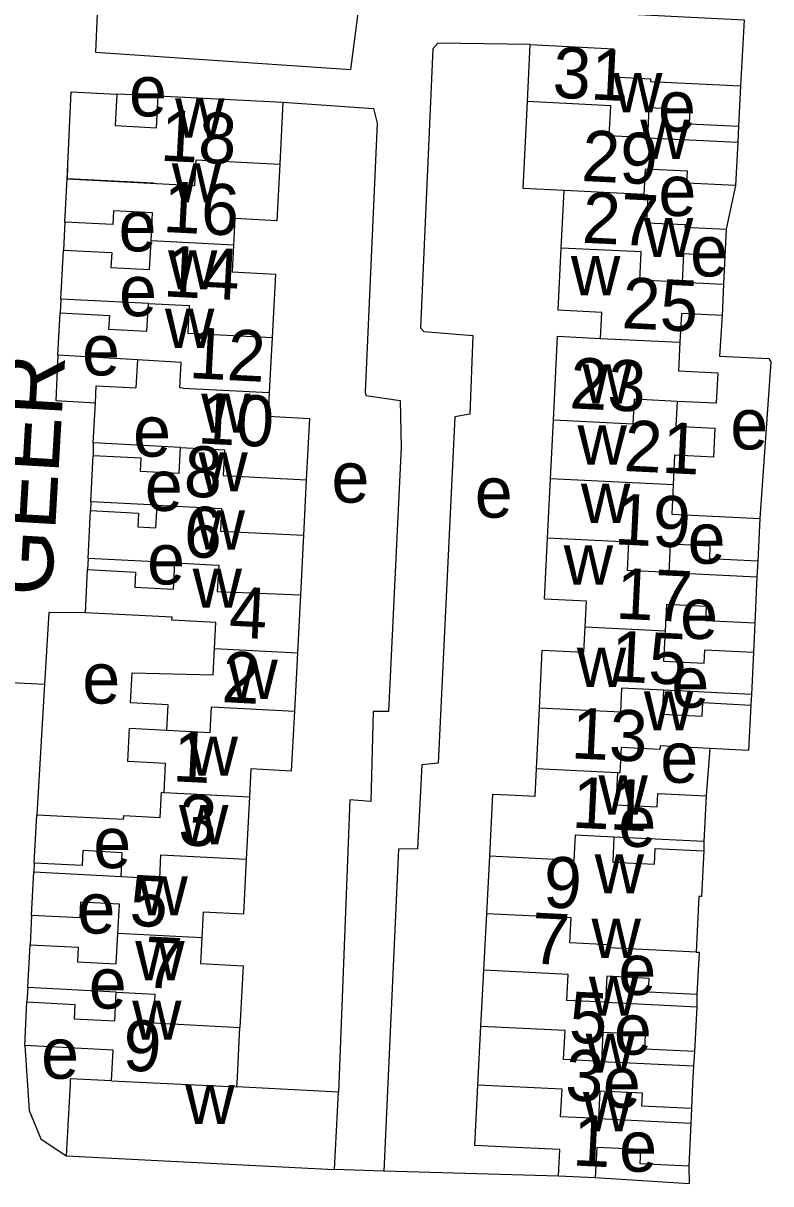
# Model space of a CAD drawing. Extents: x 163026 to 166241, y 382475 to 384501.
# Drawn here: x 164462 to 164520.6, y 383742.2 to 383833.2 of the extents above; entities that cross this region are included whole.
import ezdxf

# ---------------------------------------------------------------- set-up
doc = ezdxf.new("R2010")
doc.units = 0
for name, color, linetype in [('BLT_Basislijn', 7, 'Continuous'), ('BLT_Bebouwing', 7, 'Continuous'), ('BLT_Centroide', 7, 'Continuous'), ('BLT_Huisnummer', 7, 'Continuous'), ('BLT_Huisnummer_ tussenligend', 7, 'Continuous'), ('BLT_Onderverdeling_panden', 7, 'Continuous'), ('BLT_Straatnaam', 7, 'Continuous')]:
    doc.layers.add(name, color=color, linetype=linetype)

msp = doc.modelspace()

# ---------------------------------------------------------------- linework, layer by layer
at = {"layer": 'BLT_Basislijn'}
for p, q in [((164518.507, 383833.438), (164518.209, 383828.262)), ((164518.052, 383825.077), (164517.99, 383823.851)), ((164465.42, 383821.932), (164465.392, 383820.979)), ((164517.824, 383820.464), (164517.093, 383817.028)), ((164465.217, 383817.583), (164465.109, 383815.398)), ((164516.989, 383814.928), (164516.88, 383812.713)), ((164464.911, 383811.553), (164464.849, 383810.47)), ((164467.447, 383800.264), (164467.434, 383799.283)), ((164467.247, 383795.658), (164467.231, 383794.964)), ((164467.037, 383791.21), (164467.002, 383790.331)), ((164519.557, 383790.989), (164519.5, 383789.774)), ((164519.321, 383786.129), (164519.234, 383783.866)), ((164457.682, 383781.642), (164463.611, 383781.358)), ((164463.611, 383781.358), (164463.012, 383771.109)), ((164519.075, 383780.544), (164519.02, 383779.71)), ((164515.792, 383776.31), (164515.509, 383772.591)), ((164515.333, 383769.013), (164515.325, 383768.268)), ((164462.817, 383767.319), (164462.781, 383766.623)), ((164462.605, 383763.208), (164462.491, 383760.912)), ((164462.319, 383757.561), (164462.245, 383756.429)), ((164514.791, 383757.007), (164514.782, 383756.049)), ((164514.609, 383752.54), (164514.515, 383751.413)), ((164514.358, 383748.06), (164514.323, 383746.917)), ((164490.233, 383743.166), (164486.369, 383743.278)), ((164503.94, 383742.767), (164490.233, 383743.166))]:
    msp.add_line(p, q, dxfattribs=at)
for points in [[(164468.388, 383848.483), (164467.628, 383830.903), (164487.65, 383829.556), (164488.351, 383834.974), (164518.507, 383833.438)], [(164501.724, 383831.51), (164494.483, 383831.615), (164494.088, 383831.182), (164493.1, 383809.306), (164493.368, 383809.019), (164497.211, 383808.681), (164496.969, 383802.53), (164495.809, 383802.326), (164494.502, 383775.154), (164493.227, 383775.015), (164492.869, 383768.445), (164491.379, 383768.397), (164490.233, 383743.166)], [(164472.541, 383827.499), (164469.284, 383827.619)], [(164482.324, 383826.996), (164489.416, 383826.497), (164489.722, 383825.349), (164488.766, 383804.251), (164488.829, 383803.996), (164491.519, 383803.601), (164491.602, 383799.936), (164490.614, 383779.201), (164489.407, 383779.195), (164489.228, 383772.148), (164487.557, 383772.267), (164486.682, 383749.35)], [(164516.76, 383810.256), (164516.564, 383807.084), (164520.426, 383806.884), (164520.585, 383806.629), (164519.722, 383794.333)], [(164464.678, 383807.155), (164464.501, 383803.598), (164467.609, 383803.423)], [(164466.83, 383786.943), (164463.951, 383786.965), (164463.611, 383781.358)], [(164462.069, 383753.01), (164462.409, 383747.923), (164463.325, 383745.691), (164465.316, 383744.363)], [(164514.157, 383743.544), (164514.176, 383742.167), (164506.812, 383742.626)]]:
    msp.add_lwpolyline(points, dxfattribs=at)
at = {"layer": 'BLT_Bebouwing'}
for p, q in [((164501.503, 383827.032), (164501.724, 383831.51)), ((164518.209, 383828.262), (164518.052, 383825.077)), ((164472.541, 383827.499), (164482.324, 383826.996)), ((164482.324, 383826.996), (164482.074, 383822.138)), ((164517.99, 383823.851), (164517.824, 383820.464)), ((164465.217, 383817.583), (164465.392, 383820.98)), ((164472.175, 383820.63), (164465.392, 383820.979)), ((164504.154, 383815.544), (164504.376, 383820.054)), ((164517.093, 383817.028), (164516.989, 383814.928)), ((164464.911, 383811.553), (164465.109, 383815.398)), ((164516.88, 383812.713), (164516.76, 383810.256)), ((164464.678, 383807.155), (164464.849, 383810.47)), ((164481.476, 383808.539), (164481.254, 383804.218)), ((164503.537, 383802.055), (164503.862, 383808.634)), ((164503.862, 383808.634), (164507.239, 383808.464)), ((164470.904, 383806.783), (164464.678, 383807.155)), ((164470.904, 383806.783), (164470.779, 383804.578)), ((164467.447, 383800.264), (164467.609, 383803.423)), ((164503.313, 383797.463), (164503.537, 383802.055)), ((164467.247, 383795.658), (164467.434, 383799.283)), ((164484.156, 383797.368), (164483.933, 383793.023)), ((164503.08, 383792.789), (164503.313, 383797.463)), ((164467.037, 383791.21), (164467.231, 383794.964)), ((164519.722, 383794.333), (164519.557, 383790.989)), ((164483.933, 383793.023), (164483.692, 383788.365)), ((164466.83, 383786.943), (164467.002, 383790.331)), ((164519.5, 383789.774), (164519.321, 383786.129)), ((164483.692, 383788.365), (164483.457, 383783.81)), ((164483.457, 383783.81), (164483.222, 383779.233)), ((164519.234, 383783.866), (164519.075, 383780.544)), ((164502.199, 383774.699), (164502.432, 383779.464)), ((164479.697, 383772.518), (164479.447, 383767.631)), ((164515.509, 383772.591), (164515.333, 383769.013)), ((164462.817, 383767.319), (164463.012, 383771.109)), ((164498.316, 383763.347), (164498.537, 383767.856)), ((164515.325, 383768.268), (164515.149, 383764.697)), ((164462.605, 383763.208), (164462.781, 383766.623)), ((164498.073, 383758.908), (164498.316, 383763.347)), ((164462.319, 383757.561), (164462.491, 383760.912)), ((164514.955, 383760.327), (164514.791, 383757.007)), ((164497.844, 383754.503), (164498.073, 383758.908)), ((164462.069, 383753.01), (164462.245, 383756.429)), ((164514.782, 383756.049), (164514.609, 383752.54)), ((164514.515, 383751.413), (164514.445, 383750)), ((164486.682, 383749.35), (164478.717, 383749.758)), ((164514.445, 383750), (164514.358, 383748.06)), ((164486.369, 383743.278), (164486.682, 383749.35)), ((164514.323, 383746.917), (164514.157, 383743.544)), ((164465.316, 383744.363), (164486.369, 383743.278)), ((164506.812, 383742.626), (164503.94, 383742.767))]:
    msp.add_line(p, q, dxfattribs=at)
for points in [[(164501.724, 383831.51), (164508.258, 383831.188), (164508.149, 383828.981), (164511.159, 383828.833), (164511.148, 383828.609), (164518.209, 383828.262)], [(164465.392, 383820.98), (164465.722, 383827.803), (164469.284, 383827.619)], [(164469.284, 383827.619), (164469.157, 383825.153), (164472.413, 383824.985), (164472.541, 383827.499)], [(164504.376, 383820.054), (164501.168, 383820.21), (164501.503, 383827.032)], [(164518.052, 383825.077), (164514.198, 383825.267), (164514.254, 383826.401), (164511.025, 383826.56), (164510.909, 383824.2)], [(164510.909, 383824.2), (164517.99, 383823.851)], [(164482.074, 383822.138), (164481.846, 383817.697), (164478.55, 383817.866), (164478.442, 383815.777)], [(164517.824, 383820.464), (164513.997, 383820.653), (164514.043, 383821.586), (164510.724, 383821.749), (164510.625, 383819.745)], [(164510.625, 383819.745), (164510.941, 383819.73), (164510.834, 383817.541), (164513.859, 383817.392), (164513.849, 383817.188), (164517.093, 383817.028)], [(164471.974, 383816.111), (164472.088, 383818.316), (164469.028, 383818.473), (164468.973, 383817.39), (164465.217, 383817.583)], [(164465.109, 383815.398), (164468.89, 383815.204), (164468.829, 383814.027), (164471.859, 383813.872), (164471.974, 383816.111)], [(164478.442, 383815.777), (164478.335, 383813.689), (164481.732, 383813.514), (164481.476, 383808.539)], [(164507.239, 383808.464), (164507.339, 383810.503), (164503.914, 383810.672), (164504.154, 383815.544)], [(164516.989, 383814.928), (164513.75, 383815.087), (164513.641, 383812.873)], [(164513.641, 383812.873), (164516.88, 383812.713)], [(164471.77, 383811.2), (164464.911, 383811.553)], [(164464.849, 383810.47), (164468.708, 383810.271), (164468.653, 383809.198), (164471.658, 383809.043), (164471.77, 383811.2)], [(164516.76, 383810.256), (164513.572, 383810.413), (164513.461, 383808.159)], [(164513.461, 383808.159), (164513.35, 383805.915), (164516.425, 383805.763), (164516.307, 383803.375), (164513.239, 383803.526)], [(164467.609, 383803.423), (164467.677, 383804.738), (164470.779, 383804.578)], [(164481.254, 383804.218), (164481.158, 383802.359), (164484.403, 383802.192), (164484.156, 383797.368)], [(164513.239, 383803.526), (164513.143, 383801.585), (164516.208, 383801.434), (164516.096, 383799.159), (164513.044, 383799.309), (164512.93, 383796.99)], [(164467.434, 383799.283), (164471.171, 383799.091), (164471.117, 383798.049), (164474.175, 383797.892), (164474.28, 383799.91)], [(164474.28, 383799.91), (164467.447, 383800.264)], [(164512.93, 383796.99), (164512.816, 383794.672), (164519.722, 383794.333)], [(164467.231, 383794.964), (164471.004, 383794.77), (164470.948, 383793.682), (164472.365, 383793.609), (164472.456, 383795.39)], [(164472.456, 383795.39), (164467.247, 383795.658)], [(164506.026, 383785.853), (164506.125, 383787.849), (164502.847, 383788.01), (164503.08, 383792.789)], [(164519.557, 383790.989), (164515.792, 383791.174), (164515.84, 383792.161), (164512.693, 383792.316), (164512.585, 383790.115)], [(164467.002, 383790.331), (164470.765, 383790.133), (164470.705, 383788.958), (164473.736, 383788.802), (164473.84, 383790.86)], [(164473.84, 383790.86), (164467.037, 383791.21)], [(164512.585, 383790.115), (164519.5, 383789.774)], [(164519.321, 383786.129), (164515.489, 383786.317), (164515.545, 383787.453), (164512.402, 383787.607), (164512.3, 383785.543)], [(164476.945, 383784.144), (164477.051, 383786.195), (164473.617, 383786.372), (164473.629, 383786.595), (164466.83, 383786.943)], [(164502.432, 383779.464), (164502.657, 383784.018), (164505.928, 383783.857), (164506.026, 383785.853)], [(164512.3, 383785.543), (164512.183, 383783.162), (164515.368, 383783.006), (164515.42, 383784.047), (164519.234, 383783.866)], [(164473.22, 383777.739), (164473.323, 383779.735), (164470.37, 383779.887), (164470.492, 383782.249), (164476.84, 383782.094), (164476.945, 383784.144)], [(164512.17, 383780.885), (164512.075, 383779.001), (164515.191, 383778.848), (164515.243, 383779.9), (164519.02, 383779.71)], [(164519.075, 383780.544), (164512.17, 383780.885)], [(164519.02, 383779.71), (164518.838, 383776.16), (164515.792, 383776.31)], [(164483.222, 383779.233), (164482.98, 383774.538), (164479.81, 383774.701), (164479.697, 383772.518)], [(164473.001, 383772.861), (164473.117, 383775.124), (164470.162, 383775.276), (164470.296, 383777.889), (164473.22, 383777.739)], [(164515.792, 383776.31), (164511.905, 383776.502), (164511.892, 383776.232), (164508.842, 383776.383), (164508.743, 383774.376), (164508.561, 383774.385)], [(164498.537, 383767.856), (164498.792, 383772.73), (164500, 383772.669), (164502.094, 383772.558), (164502.199, 383774.699)], [(164508.561, 383774.385), (164508.438, 383771.88), (164511.669, 383771.721), (164511.721, 383772.777), (164515.509, 383772.591)], [(164463.012, 383771.109), (164469.824, 383770.758), (164469.838, 383771.037), (164472.685, 383770.891), (164472.787, 383772.872), (164473.001, 383772.861)], [(164508.28, 383769.36), (164508.183, 383767.387), (164511.458, 383767.226), (164511.518, 383768.456), (164515.325, 383768.268)], [(164515.333, 383769.013), (164508.28, 383769.36)], [(164469.629, 383766.271), (164469.725, 383768.134), (164466.64, 383768.293), (164466.58, 383767.125), (164462.817, 383767.319)], [(164479.447, 383767.631), (164479.223, 383763.313), (164476.071, 383763.475), (164475.967, 383761.453)], [(164462.781, 383766.623), (164469.629, 383766.271)], [(164469.374, 383761.792), (164469.492, 383764.094), (164466.453, 383764.251), (164466.389, 383763.013), (164462.605, 383763.208)], [(164515.149, 383764.697), (164514.929, 383764.708), (164514.735, 383760.338)], [(164462.491, 383760.912), (164466.274, 383760.718), (164466.215, 383759.566), (164469.251, 383759.41), (164469.374, 383761.792)], [(164475.967, 383761.453), (164475.863, 383759.432), (164479.199, 383759.261), (164478.953, 383754.431)], [(164514.735, 383760.338), (164514.955, 383760.327)], [(164514.791, 383757.007), (164510.981, 383757.195), (164511.034, 383758.278), (164507.733, 383758.44), (164507.633, 383756.401)], [(164462.245, 383756.429), (164466.012, 383756.235), (164465.954, 383755.103), (164469.136, 383754.939), (164469.253, 383757.204)], [(164469.253, 383757.204), (164462.319, 383757.561)], [(164507.633, 383756.401), (164514.782, 383756.049)], [(164478.717, 383749.758), (164478.722, 383750), (164478.953, 383754.431)], [(164497.606, 383749.912), (164497.844, 383754.503)], [(164514.609, 383752.54), (164510.693, 383752.733), (164510.748, 383753.867), (164507.412, 383754.031), (164507.3, 383751.77)], [(164468.887, 383750.234), (164469.012, 383752.653), (164462.069, 383753.01)], [(164507.3, 383751.77), (164514.515, 383751.413)], [(164468.887, 383750.234), (164465.643, 383750.401), (164465.622, 383750), (164465.316, 383744.363)], [(164500, 383745.051), (164497.362, 383745.178), (164497.606, 383749.912)], [(164514.358, 383748.06), (164510.482, 383748.251), (164510.533, 383749.276), (164507.187, 383749.441), (164507.08, 383747.275)], [(164507.08, 383747.275), (164514.323, 383746.917)], [(164503.94, 383742.767), (164504.043, 383744.853), (164500, 383745.051)], [(164514.157, 383743.544), (164510.33, 383743.732), (164510.385, 383744.853), (164506.93, 383745.023), (164506.812, 383742.626)]]:
    msp.add_lwpolyline(points, dxfattribs=at)
at = {"layer": 'BLT_Onderverdeling_panden'}
for p, q in [((164510.625, 383819.745), (164504.376, 383820.054)), ((164478.442, 383815.777), (164471.974, 383816.111)), ((164507.239, 383808.464), (164513.461, 383808.159)), ((164474.492, 383804.567), (164481.254, 383804.218)), ((164512.93, 383796.99), (164503.313, 383797.463)), ((164506.026, 383785.853), (164512.3, 383785.543)), ((164476.945, 383784.144), (164483.457, 383783.81)), ((164508.561, 383774.385), (164502.199, 383774.699)), ((164473.001, 383772.861), (164479.697, 383772.518)), ((164475.967, 383761.453), (164469.374, 383761.792)), ((164468.887, 383750.234), (164478.717, 383749.758))]:
    msp.add_line(p, q, dxfattribs=at)
for points in [[(164510.909, 383824.2), (164507.919, 383824.348), (164508.037, 383826.708), (164501.503, 383827.032)], [(164465.392, 383820.98), (164475.413, 383820.463), (164475.509, 383822.478), (164482.074, 383822.138)], [(164513.641, 383812.873), (164510.308, 383813.04), (164510.414, 383815.245), (164504.154, 383815.544)], [(164471.77, 383811.2), (164474.967, 383811.035), (164474.866, 383808.88), (164481.476, 383808.539)], [(164474.492, 383804.567), (164474.227, 383804.581), (164474.33, 383806.578), (164470.904, 383806.783)], [(164513.239, 383803.526), (164509.861, 383803.69), (164509.768, 383801.75), (164503.537, 383802.055)], [(164474.28, 383799.91), (164477.748, 383799.73), (164477.644, 383797.709), (164484.156, 383797.368)], [(164472.456, 383795.39), (164477.511, 383795.128), (164477.419, 383793.353), (164483.933, 383793.023)], [(164512.585, 383790.115), (164509.34, 383790.275), (164509.448, 383792.475), (164503.08, 383792.789)], [(164473.84, 383790.86), (164477.282, 383790.683), (164477.175, 383788.618), (164483.692, 383788.365)], [(164512.17, 383780.885), (164508.888, 383781.047), (164508.796, 383779.158), (164502.432, 383779.464)], [(164473.22, 383777.739), (164476.606, 383777.566), (164476.709, 383779.563), (164483.222, 383779.233)], [(164508.28, 383769.36), (164505.25, 383769.508), (164505.147, 383767.533), (164498.537, 383767.856)], [(164469.629, 383766.271), (164472.674, 383766.112), (164472.756, 383767.978), (164479.447, 383767.631)], [(164514.735, 383760.338), (164507.859, 383760.676), (164507.871, 383760.917), (164504.824, 383761.067), (164504.92, 383763.023), (164498.316, 383763.347)], [(164507.633, 383756.401), (164504.577, 383756.55), (164504.683, 383758.588), (164498.073, 383758.908)], [(164469.253, 383757.204), (164472.276, 383757.05), (164472.177, 383754.782), (164478.953, 383754.431)], [(164507.3, 383751.77), (164504.336, 383751.916), (164504.454, 383754.176), (164497.844, 383754.503)], [(164507.08, 383747.275), (164504.103, 383747.423), (164504.216, 383749.586), (164497.606, 383749.912)]]:
    msp.add_lwpolyline(points, dxfattribs=at)

# ---------------------------------------------------------------- texts
at = {"layer": 'BLT_Centroide'}
for s, p in [('e', (164470.248, 383825.878)), ('w', (164508.214, 383826.197)), ('e', (164511.737, 383824.688)), ('w', (164473.867, 383824.219)), ('w', (164510.359, 383822.537)), ('w', (164473.609, 383819.125)), ('e', (164511.77, 383818.066)), ('e', (164469.431, 383815.292)), ('w', (164510.633, 383814.839)), ('e', (164514.258, 383813.327)), ('w', (164473.312, 383812.312)), ('w', (164504.913, 383811.844)), ('e', (164469.469, 383810.208)), ('w', (164473.07, 383807.719)), ('e', (164466.566, 383805.566)), ('w', (164505.815, 383803.353)), ('w', (164475.914, 383801.062)), ('e', (164470.569, 383799.196)), ('e', (164517.406, 383799.758)), ('w', (164505.432, 383798.57)), ('w', (164475.695, 383796.469)), ('e', (164486.128, 383795.589)), ('e', (164471.492, 383794.937)), ('e', (164497.369, 383794.41)), ('w', (164505.698, 383793.992)), ('w', (164475.477, 383791.906)), ('e', (164514.061, 383790.794)), ('e', (164471.668, 383789.171)), ('w', (164504.348, 383789.156)), ('w', (164475.242, 383787.344)), ('e', (164513.474, 383784.896)), ('w', (164505.375, 383781.14)), ('w', (164478.046, 383780.189)), ('e', (164466.585, 383779.831)), ('e', (164512.784, 383779.506)), ('w', (164510.633, 383777.719)), ('w', (164474.923, 383774.163)), ('e', (164511.918, 383773.614)), ('w', (164507.07, 383771.125)), ('w', (164474.175, 383768.797)), ('e', (164508.627, 383768.588)), ('e', (164467.446, 383766.92)), ('w', (164506.773, 383764.938)), ('w', (164470.992, 383763.212)), ('e', (164466.205, 383761.794)), ('w', (164506.531, 383759.875)), ('w', (164470.742, 383758.125)), ('e', (164508.627, 383756.977)), ('e', (164467.094, 383755.909)), ('w', (164506.32, 383755.344)), ('w', (164470.5, 383753.469)), ('e', (164508.281, 383752.297)), ('w', (164506.07, 383750.875)), ('e', (164463.356, 383750.403)), ('e', (164507.415, 383748.138)), ('w', (164474.667, 383746.844)), ('w', (164505.859, 383746.281)), ('e', (164508.691, 383743.112))]:
    msp.add_text(s, height=4, dxfattribs=at).set_placement(p)
at = {"layer": 'BLT_Huisnummer'}
for s, height, rotation, p in [('31', 4, 357.19626, (164503.419, 383827.359)), ('18', 4, 357.07255, (164472.64, 383822.409)), ('14', 4, 357.06134, (164472.891, 383811.767)), ('25', 4, 357.19626, (164508.847, 383809.279)), ('10', 3.9999, 357.05071, (164475.578, 383800.24)), ('21', 4, 357.19626, (164509.009, 383798.075)), ('6', 4, 357.05071, (164474.48, 383791.351)), ('17', 4, 357.19626, (164508.37, 383786.497)), ('2', 4, 357.05071, (164477.472, 383779.952)), ('13', 4, 357.19626, (164504.871, 383775.543)), ('1', 4, 357.06761, (164473.62, 383773.741)), ('9', 4, 357.19626, (164502.686, 383763.864)), ('5', 4, 357.05655, (164470.232, 383762.421)), ('5', 4, 357.19626, (164504.708, 383753.258)), ('9', 4, 357.22772, (164469.718, 383751.066)), ('1', 4, 357.19626, (164504.982, 383743.61))]:
    msp.add_text(s, height=height, rotation=rotation, dxfattribs=at).set_placement(p)
at = {"layer": 'BLT_Huisnummer_ tussenligend'}
for s, height, rotation, p in [('29', 4, 357.19626, (164505.686, 383820.816)), ('16', 4, 357.06134, (164472.844, 383816.82)), ('27', 4, 357.19626, (164505.73, 383815.975)), ('12', 3.9999, 357.05071, (164474.904, 383805.359)), ('23', 4, 357.19626, (164504.749, 383802.99)), ('8', 4, 357.05071, (164474.492, 383796.087)), ('19', 4, 357.19626, (164508.258, 383792.326)), ('4', 4, 357.05071, (164478.031, 383785.038)), ('15', 4, 357.19626, (164507.957, 383781.579)), ('11', 4, 357.19626, (164504.932, 383770.107)), ('3', 4, 357.06761, (164474.07, 383768.746)), ('7', 4, 357.19626, (164501.73, 383759.451)), ('7', 4, 357.05655, (164471.359, 383757.579)), ('3', 4, 357.19626, (164504.412, 383748.733))]:
    msp.add_text(s, height=height, rotation=rotation, dxfattribs=at).set_placement(p)
at = {"layer": 'BLT_Straatnaam'}
msp.add_text('GEER', height=4.9999, rotation=86.6842, dxfattribs=at).set_placement((164464.152, 383788.161))

doc.saveas('drawing.dxf')
